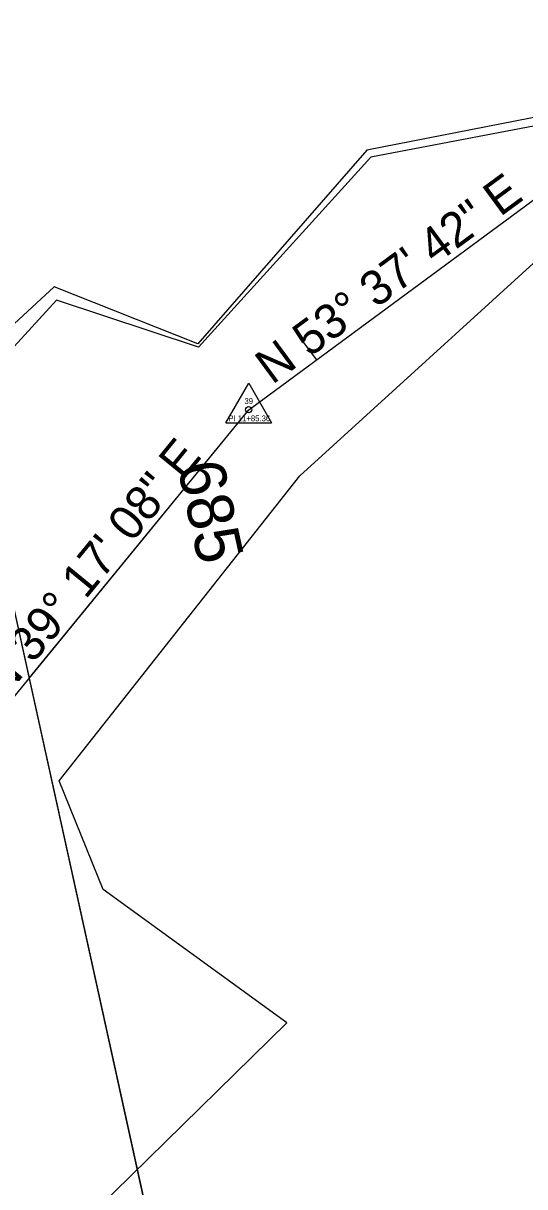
# Model space of a CAD drawing. Extents: x 2519952 to 2531965, y 848341 to 887632.
# Drawn here: x 2528499.3 to 2528586.3, y 851960.5 to 852162.2 of the extents above; entities that cross this region are included whole.
import ezdxf

# ---------------------------------------------------------------- set-up
doc = ezdxf.new("R2010")
doc.units = 0
for name, color, linetype in [('RD_EX_DV_Prop', 7, 'Continuous'), ('RD_EX_H2O', 7, 'Continuous'), ('RD_EX_Misc', 7, 'Continuous'), ('RD_EX_RW', 7, 'Continuous'), ('RD_HC_Cl', 7, 'Continuous'), ('RD_HC_Data', 7, 'Continuous'), ('RD_HC_Data_Tic', 7, 'Continuous'), ('RD_HC_TX_Sta50', 7, 'Continuous'), ('RD_HC_txCode', 7, 'Continuous'), ('RD_SMD_Locator', 7, 'Continuous')]:
    doc.layers.add(name, color=color, linetype=linetype)

msp = doc.modelspace()

# ---------------------------------------------------------------- linework, layer by layer
at = {"layer": 'RD_EX_DV_Prop'}
for p, q in [((2528538.4, 852095.17), (2528593.3, 852135.6)), ((2528484.88, 852118.66), (2528549.4, 851825.68)), ((2528500.31, 852048.61), (2528538.4, 852095.17))]:
    msp.add_line(p, q, dxfattribs=at)
at = {"layer": 'RD_EX_H2O'}
for points in [[(2528499.97, 851944.76), (2528544.99, 851988.87), (2528513.17, 852011.98), (2528505.55, 852030.86), (2528547.24, 852083.68), (2528591.62, 852124.02), (2528635.59, 852119.4), (2528663.79, 852103.71), (2528692.12, 852114.02), (2528694.26, 852117.1), (2528712.97, 852122.22), (2528745.96, 852136.25), (2528808.96, 852155.61), (2528854.52, 852216.53)], [(2528719.59, 851999.09), (2528691.1, 852047.72), (2528711.96, 852086.66), (2528686.69, 852125.57), (2528637.99, 852160.23), (2528595.34, 852145.76), (2528559.57, 852138.95), (2528529.72, 852106.03), (2528505.05, 852114.18), (2528485.4, 852092.73), (2528481.66, 852040.55)]]:
    msp.add_lwpolyline(points, dxfattribs=at)
at = {"layer": 'RD_EX_Misc'}
msp.add_lwpolyline([(2528721.04, 851999.29), (2528692.03, 852048.08), (2528712.68, 852087), (2528694.26, 852117.1), (2528687.66, 852126.5), (2528638.26, 852161.91), (2528594.97, 852147.21), (2528558.87, 852140.18), (2528529.59, 852106.6), (2528504.69, 852116.44), (2528482.38, 852095.87), (2528476.12, 852043.21)], dxfattribs=at)
at = {"layer": 'RD_EX_RW'}
msp.add_line((2528484.89, 852118.66), (2528549.4, 851825.67), dxfattribs=at)
at = {"layer": 'RD_HC_Cl'}
for p, q in [((2528538.4, 852095.17), (2528593.3, 852135.6)), ((2528490.84, 852037.04), (2528538.4, 852095.17))]:
    msp.add_line(p, q, dxfattribs=at)
at = {"layer": 'RD_HC_Data'}
for p, q in [((2528534.43, 852092.88), (2528538.4, 852099.76)), ((2528538.4, 852099.76), (2528542.37, 852092.88)), ((2528534.43, 852092.88), (2528542.37, 852092.88))]:
    msp.add_line(p, q, dxfattribs=at)
msp.add_circle((2528538.4, 852095.17), 0.529, dxfattribs=at)
at = {"layer": 'RD_HC_Data_Tic'}
msp.add_line((2528550.18, 852103.85), (2528547.81, 852107.07), dxfattribs=at)
at = {"layer": 'RD_SMD_Locator'}
for centre in [(2528558.87, 852140.18), (2528559.57, 852138.95), (2528504.69, 852116.44), (2528505.05, 852114.18), (2528529.59, 852106.6), (2528529.72, 852106.03), (2528538.4, 852095.17), (2528547.24, 852083.68), (2528505.55, 852030.86), (2528513.17, 852011.98), (2528544.99, 851988.87)]:
    msp.add_circle(centre, 0.001, dxfattribs=at)

# ---------------------------------------------------------------- texts
at = {"layer": 'RD_HC_Data'}
for s, rotation, p in [('N 53%%d 37\' 42" E', 36.3717, (2528542.47, 852099.41)), ('N 39%%d 17\' 08" E', 50.7144, (2528495.93, 852044.84))]:
    msp.add_text(s, height=6, rotation=rotation, dxfattribs=at).set_placement(p)
at = {"layer": 'RD_HC_TX_Sta50'}
msp.add_text('685', height=8, rotation=282.4185, dxfattribs=at).set_placement((2528525.99, 852085.42))
at = {"layer": 'RD_HC_txCode'}
for s, p in [('39', (2528537.66, 852096.17)), ('PI 11+85.36', (2528534.88, 852093.17))]:
    msp.add_text(s, height=1, dxfattribs=at).set_placement(p)

doc.saveas('drawing.dxf')
